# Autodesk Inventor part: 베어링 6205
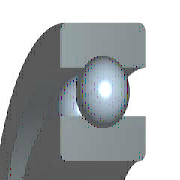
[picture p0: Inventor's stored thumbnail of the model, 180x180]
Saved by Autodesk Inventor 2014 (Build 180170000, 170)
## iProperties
Company: 한국ATC센터
IsCustomPart: 1
Created: 2009-02
Part Number: 베어링 6205
Material: 강, 연강
Description: 깊은 그루브 볼 베어링
Document SubType Name: Modeling
Standard: KS B 2023
Designer: KYOUNG IL JANG
Standards Organization: KS
Language: ko-KR
Size Designation: 6205 - 25 x 52 x 15
Categories: <MemberInstance><Categories><Category DisplayName="샤프트 부품" InternalName="7f7aeb1f-a693-4053-b835-cee3144e0d98" Mnemonic="SHFT"><Category DisplayName="베어링" Inter
Density: 1 g/cm^3
Appearance: 강철
Author: KYOUNG IL JANG
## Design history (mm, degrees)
sketch "스케치" dims "d0" = 7.02 (= -0.26 x WD + 0.26 x BD)
  geometry: L1 (3.99, 19.25)-(11.01, 19.25); L2 (7.5, 19.25)-(7.5, 15.74); L3 (7.5, 19.25)-(7.5, 22.76); L4 (4.892, 16.901)-(0, 16.901); L5 (0, 12.5)-(15, 12.5); L6 (4.892, 21.599)-(0, 21.599); L7 (0, 26)-(15, 26); L8 (15, 12.5)-(15, 16.901); L9 (10.108, 16.901)-(15, 16.901); L10 (10.108, 21.599)-(15, 21.599); L11 (15, 26)-(15, 21.599); L12 (-1.4, 0)-(8.4, 0) reference; L13 (0, -0.3)-(0, 5.3) reference
  constraints: 22 end point, 4 point on line, 2 collinear, 2 perpendicular, 2 symmetric about line, 1 midpoint, 1 parallel, 14 other
  dimensions: "d9" = 25 diameter of L5 L12 (= WD); "d11" = 52 diameter of L7 L12 (= BD); "d12" = 15 distance between parallel lines of L8 L13 (= KB); "d13" = 33.802 diameter of L9 L12 (= 0.326 x BD + 0.674 x WD)
revolve "본체" stored, may be unused: angle "d6" = 90 deg
revolve "볼" stored, may be unused: angle "d7" = 90 deg
pattern_circular "IDS_ARRAYBALL[SIMPL:T]" dims angle "d3" = 360 deg
body "Solid1"
fillet "모깎기1" dims "d1" = 1 (= KRS)
other parameters: "WD" = 25 [user parameter; used in 5 equation terms], "BD" = 52 [user parameter; used in 5 equation terms], "KB" = 15 [user parameter; used in 1 equation term], "KRS" = 1 [user parameter; used in 1 equation term], "d4" = 0, "d5" = 0, "d8" = 0, "d14" = 0, "d15" = 0, "BBA" = 0 [user parameter], "BC0" = 7800000 [user parameter], "BC" = 1.4e+07 [user parameter], "BR" = 26 (= 0.5 x BD) [user parameter], "WR" = 12.5 (= 0.5 x WD) [user parameter]
